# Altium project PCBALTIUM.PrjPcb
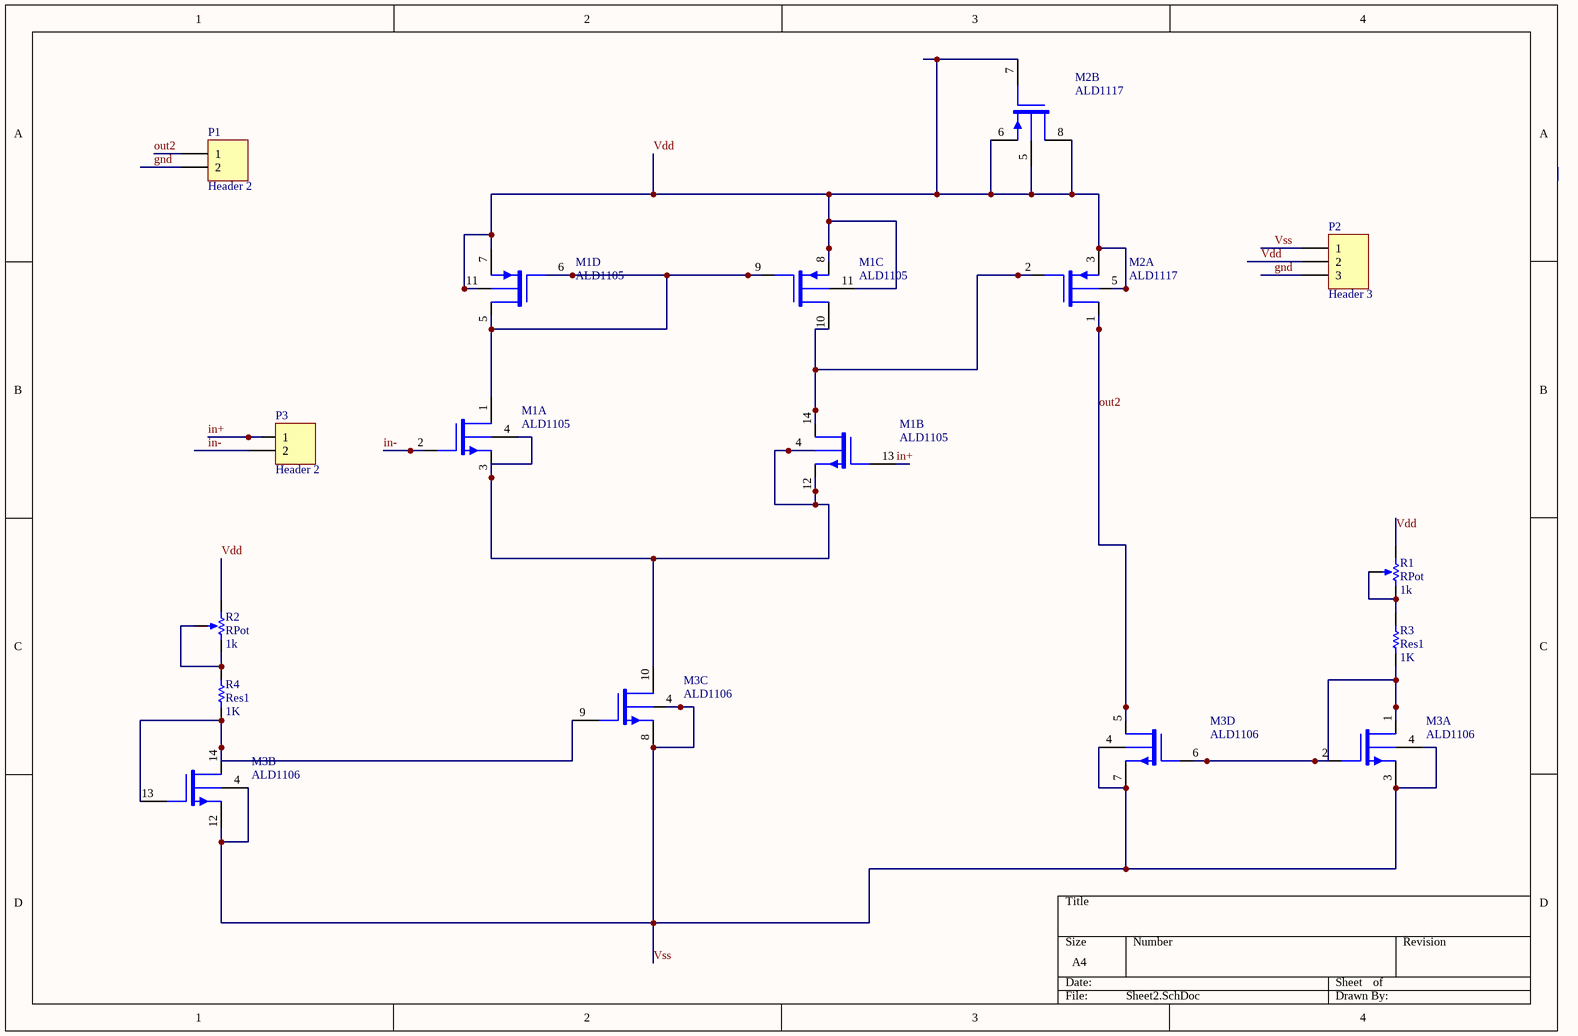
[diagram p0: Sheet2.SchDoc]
1 sheet, 10 parts. Net scope: global (net labels, ports and power ports of the same name join across sheets).
Board file: PCB1.PcbDoc

## Sheet Sheet2.SchDoc
size A4

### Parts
M1  ALD1105  [DIP-14]  (parts A,B,C,D of 4)
M2  ALD1117  [DIP-8]  (parts A,B of 2)
M3  ALD1106  [DIP-14]  (parts A,B,C,D of 4)
P1  Header 2  [HDR1X2]
P2  Header 3  [HDR1X3]
P3  Header 2  [HDR1X2]
R1  RPot  value 1k  [VR5]
R2  RPot  value 1k  [VR5]
R3  Res1  value 1K  [AXIAL-0.3]
R4  Res1  value 1K  [AXIAL-0.3]

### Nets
gnd: P1.2 P2.3
in+: M1.13(GN2) P3.1
in-: M1.2(GN1) P3.2
out2: M2.1(DP1) M3.5(DN4) P1.1
Vdd: M1.7(SP1) M1.8(SP2) M1.11(V+) M2.3(SP1) M2.5(V+) M2.6(SP2) M2.7(GP2) M2.8(DP2) P2.2 R1.1(TOP) R2.1(TOP)
Vss: M3.3(SN1) M3.4(V-) M3.7(SN4) M3.8(SN3) M3.12(SN2) P2.1
NetM1_1: M1.1(DN1) M1.5(DP1) M1.6(GP1) M1.9(GP2)
NetM1_3: M1.3(SN1) M1.4(V-) M1.12(SN2) M3.10(DN3)
NetM1_10: M1.10(DP2) M1.14(DN2) M2.2(GP1)
NetM3_1: M3.1(DN1) M3.2(GN1) M3.6(GN4) R3.2
NetM3_9: M3.9(GN3) M3.13(GN2) M3.14(DN2) R4.2
NetR1_2: R1.2(TAP) R1.3(BOT) R3.1
NetR2_2: R2.2(TAP) R2.3(BOT) R4.1

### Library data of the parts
M1 = ALD1105: Dual P-channel and dual N-channel matched MOSFET array
M2 = ALD1117: Dual P-channel matched MOSFET array
M3 = ALD1106: Quad N-channel matched MOSFET array
P1 P3 = Header 2: Header, 2-Pin
P2 = Header 3: Header, 3-Pin
R1 R2 = RPot: Potentiometer; Sim Note: Enter the Resistance value and the set point into parameter fields.; Set Position: 0.5
R3 R4 = Res1: Resistor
